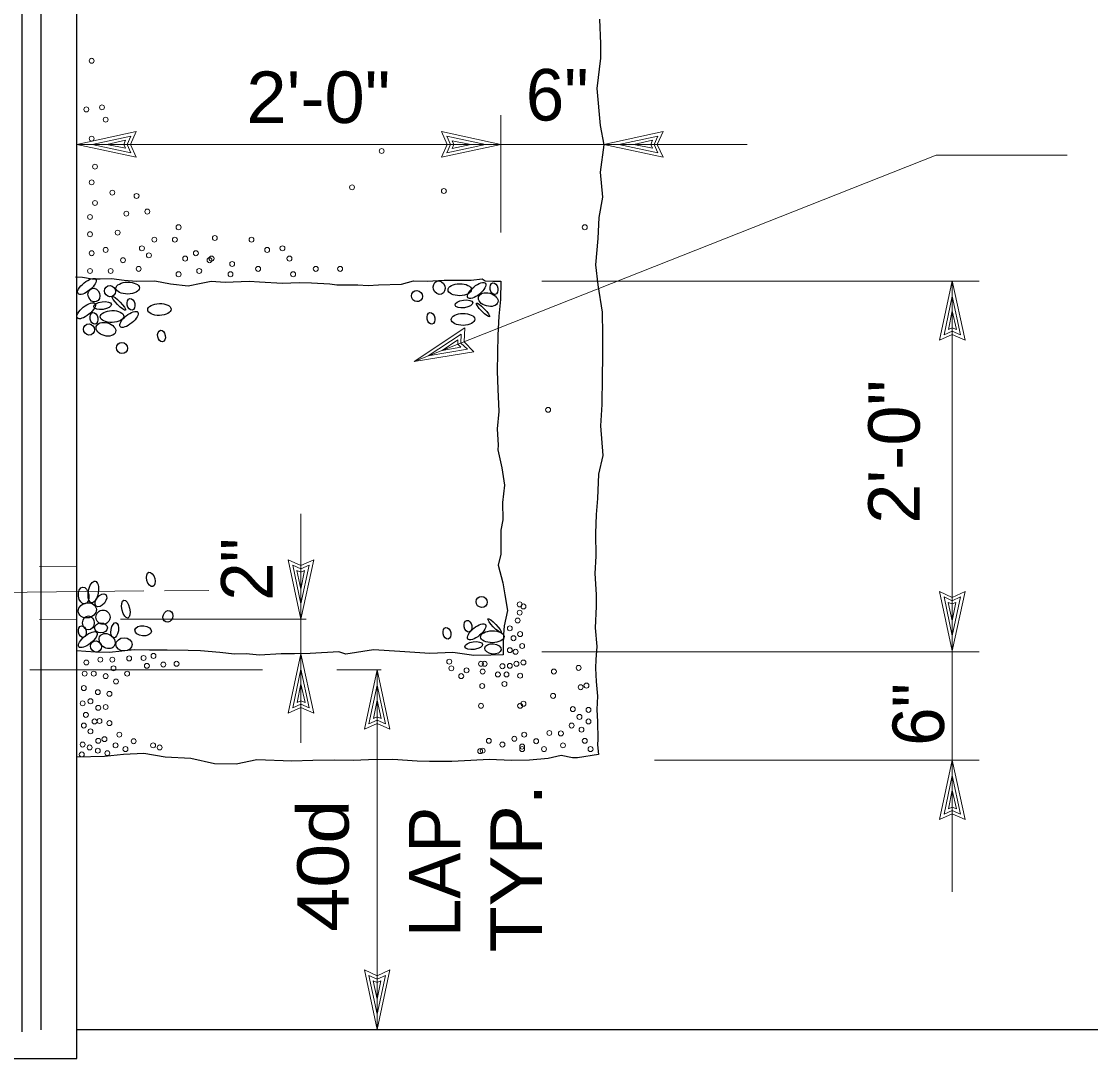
# Model space of a CAD drawing. Extents: x -28.1 to 13.9, y -16.1 to 13.9.
# Drawn here: x -6.926 to -4.33, y -10.785 to -8.269 of the extents above; entities that cross this region are included whole.
import ezdxf
from ezdxf.enums import TextEntityAlignment as Align

# ---------------------------------------------------------------- set-up
doc = ezdxf.new("R2010")
doc.units = 0
doc.header["$LTSCALE"] = 0.05
doc.linetypes.add('MEDIUM_DASHED', pattern=[4.5, 3, -1.5])
doc.layers.add('1', color=7, linetype='Continuous', lineweight=13)

msp = doc.modelspace()

# ---------------------------------------------------------------- linework, layer by layer
at = {"layer": '1', "lineweight": 25}
for p, q in [((-6.79104, -10.78531), (-6.79104, -2.71131)), ((-6.87804, -10.71531), (-6.87804, -2.77031)), ((-6.92404, -10.72031), (-6.92404, -6.69531)), ((-6.79004, -10.71431), (-2.77004, -10.71431)), ((-7.63204, -10.78531), (-6.79104, -10.78531))]:
    msp.add_line(p, q, dxfattribs=at)
at = {"layer": '1'}
for p, q in [((-5.76204, -8.78131), (-5.76204, -8.49631)), ((-6.79104, -8.56731), (-6.64704, -8.53631)), ((-5.76204, -8.56731), (-5.90604, -8.53631)), ((-5.51204, -8.56731), (-5.36804, -8.53631)), ((-6.75404, -8.56731), (-6.66004, -8.54731)), ((-6.71804, -8.56731), (-6.67304, -8.55731)), ((-6.67304, -8.55731), (-6.67704, -8.56731)), ((-6.66004, -8.54731), (-6.66904, -8.56731)), ((-5.79904, -8.56731), (-5.89304, -8.54731)), ((-5.88404, -8.56731), (-5.89304, -8.54731)), ((-5.83504, -8.56731), (-5.88004, -8.55831)), ((-5.87604, -8.56731), (-5.88004, -8.55831)), ((-5.47504, -8.56731), (-5.38104, -8.54731)), ((-5.43904, -8.56731), (-5.39404, -8.55731)), ((-5.39404, -8.55731), (-5.39804, -8.56731)), ((-5.38104, -8.54731), (-5.39004, -8.56731)), ((-6.79104, -8.56731), (-6.64704, -8.59831)), ((-6.75404, -8.56731), (-6.66004, -8.58731)), ((-6.71804, -8.56731), (-6.67304, -8.57631)), ((-6.67704, -8.56731), (-6.67304, -8.57631)), ((-6.66904, -8.56731), (-6.66004, -8.58731)), ((-5.76204, -8.56731), (-5.90604, -8.59831)), ((-5.79904, -8.56731), (-5.89304, -8.58731)), ((-5.89304, -8.58731), (-5.88404, -8.56731)), ((-5.83504, -8.56731), (-5.88004, -8.57731)), ((-5.88004, -8.57731), (-5.87604, -8.56731)), ((-5.51204, -8.56731), (-5.36804, -8.59831)), ((-5.47504, -8.56731), (-5.38104, -8.58731)), ((-5.43904, -8.56731), (-5.39404, -8.57631)), ((-5.39804, -8.56731), (-5.39404, -8.57631)), ((-5.39004, -8.56731), (-5.38104, -8.58731)), ((-4.70504, -8.59331), (-4.38704, -8.59331)), ((-5.66204, -8.89931), (-4.60104, -8.89931)), ((-4.66604, -8.89831), (-4.69704, -9.04231)), ((-4.66604, -8.89831), (-4.63504, -9.04231)), ((-4.66604, -8.93531), (-4.68604, -9.02931)), ((-4.66604, -8.93531), (-4.64604, -9.02931)), ((-4.66604, -8.97131), (-4.67504, -9.01631)), ((-4.66604, -8.97131), (-4.65604, -9.01631)), ((-5.93804, -9.08031), (-5.85804, -9.02731)), ((-5.85804, -9.02731), (-5.85904, -9.04931)), ((-4.66604, -9.02031), (-4.68604, -9.02931)), ((-4.66604, -9.01231), (-4.67504, -9.01631)), ((-4.65604, -9.01631), (-4.66604, -9.01231)), ((-4.64604, -9.02931), (-4.66604, -9.02031)), ((-5.90404, -9.06731), (-5.86604, -9.04131)), ((-5.86604, -9.04131), (-5.86604, -9.05231)), ((-5.86604, -9.05231), (-5.85904, -9.05931)), ((-5.85904, -9.04931), (-5.84304, -9.06431)), ((-5.97204, -9.09431), (-5.82704, -9.07031)), ((-5.93804, -9.08031), (-5.84304, -9.06431)), ((-5.90404, -9.06731), (-5.85904, -9.05931)), ((-6.24704, -9.71931), (-6.27804, -9.57531)), ((-6.24704, -9.71931), (-6.21604, -9.57531)), ((-6.24704, -9.68231), (-6.26704, -9.58831)), ((-6.26704, -9.58831), (-6.24704, -9.59731)), ((-6.24704, -9.64631), (-6.25704, -9.60131)), ((-6.25704, -9.60131), (-6.24704, -9.60531)), ((-6.24704, -9.68231), (-6.22704, -9.58831)), ((-6.24704, -9.59731), (-6.22704, -9.58831)), ((-6.24704, -9.64631), (-6.23804, -9.60131)), ((-6.24704, -9.60531), (-6.23804, -9.60131)), ((-7.10304, -9.65531), (-6.62804, -9.65031)), ((-6.57804, -9.65031), (-6.47104, -9.64931)), ((-4.66604, -9.79631), (-4.69704, -9.65231)), ((-4.66604, -9.79631), (-4.63504, -9.65231)), ((-4.66604, -9.75931), (-4.68604, -9.66531)), ((-4.68604, -9.66531), (-4.66604, -9.67431)), ((-4.66604, -9.72331), (-4.67604, -9.67831)), ((-4.67604, -9.67831), (-4.66604, -9.68231)), ((-4.66604, -9.75931), (-4.64604, -9.66531)), ((-4.66604, -9.67431), (-4.64604, -9.66531)), ((-4.66604, -9.72331), (-4.65704, -9.67831)), ((-4.66604, -9.68231), (-4.65704, -9.67831)), ((-6.68504, -9.71931), (-6.23404, -9.71931)), ((-6.24704, -9.80331), (-6.27804, -9.94731)), ((-6.24704, -9.80331), (-6.21604, -9.94731)), ((-5.66204, -9.79831), (-4.60104, -9.79831)), ((-6.90504, -9.84231), (-6.34004, -9.84231)), ((-6.24704, -9.84031), (-6.26704, -9.93431)), ((-6.24704, -9.84031), (-6.22704, -9.93431)), ((-6.16004, -9.84231), (-6.05204, -9.84231)), ((-6.06204, -9.84231), (-6.09304, -9.98631)), ((-6.06204, -10.71431), (-6.06204, -9.84231)), ((-6.06204, -9.84231), (-6.03104, -9.98631)), ((-6.24704, -9.87631), (-6.25604, -9.92131)), ((-6.24704, -9.87631), (-6.23704, -9.92131)), ((-6.06204, -9.87931), (-6.08204, -9.97331)), ((-6.06204, -9.87931), (-6.04204, -9.97331)), ((-6.24704, -9.92531), (-6.26704, -9.93431)), ((-6.24704, -9.91731), (-6.25604, -9.92131)), ((-6.23704, -9.92131), (-6.24704, -9.91731)), ((-6.22704, -9.93431), (-6.24704, -9.92531)), ((-6.06204, -9.91531), (-6.07104, -9.96031)), ((-6.06204, -9.91531), (-6.05204, -9.96031)), ((-6.06204, -9.96431), (-6.08204, -9.97331)), ((-6.06204, -9.95631), (-6.07104, -9.96031)), ((-6.05204, -9.96031), (-6.06204, -9.95631)), ((-6.04204, -9.97331), (-6.06204, -9.96431)), ((-5.38904, -10.06131), (-4.60104, -10.06131)), ((-4.66604, -10.06131), (-4.69704, -10.20531)), ((-4.66604, -10.06131), (-4.63504, -10.20531)), ((-4.66604, -10.09831), (-4.68604, -10.19231)), ((-4.66604, -10.09831), (-4.64604, -10.19231)), ((-4.66604, -10.13431), (-4.67504, -10.17931)), ((-4.66604, -10.13431), (-4.65604, -10.17931)), ((-4.66604, -10.18331), (-4.68604, -10.19231)), ((-4.66604, -10.17531), (-4.67504, -10.17931)), ((-4.65604, -10.17931), (-4.66604, -10.17531)), ((-4.64604, -10.19231), (-4.66604, -10.18331)), ((-6.06204, -10.71431), (-6.09304, -10.57031)), ((-6.06204, -10.67731), (-6.08204, -10.58331)), ((-6.08204, -10.58331), (-6.06204, -10.59231)), ((-6.06204, -10.71431), (-6.03104, -10.57031)), ((-6.06204, -10.67731), (-6.04204, -10.58331)), ((-6.06204, -10.59231), (-6.04204, -10.58331)), ((-6.06204, -10.64131), (-6.07204, -10.59631)), ((-6.07204, -10.59631), (-6.06204, -10.60031)), ((-6.06204, -10.64131), (-6.05304, -10.59631)), ((-6.06204, -10.60031), (-6.05304, -10.59631))]:
    msp.add_line(p, q, dxfattribs=at)
at = {"layer": '1', "linetype": 'MEDIUM_DASHED'}
for p, q in [((-7.63204, -9.59831), (-6.79104, -9.59031)), ((-7.63204, -9.72731), (-6.79104, -9.71931))]:
    msp.add_line(p, q, dxfattribs=at)
at = {"layer": '1', "lineweight": 25}
for points in [[(-5.52204, -8.26331), (-5.52004, -8.32331), (-5.52004, -8.35831), (-5.52904, -8.43131), (-5.52104, -8.52131), (-5.51204, -8.56831), (-5.52104, -8.63431), (-5.51504, -8.69531), (-5.52404, -8.74431), (-5.52604, -8.79531), (-5.53204, -8.85931), (-5.52604, -8.90831), (-5.51604, -8.97431), (-5.51504, -9.02931), (-5.51504, -9.08131), (-5.51604, -9.13231), (-5.51704, -9.19831), (-5.52004, -9.25031), (-5.51404, -9.32231), (-5.52504, -9.36731), (-5.52704, -9.42631), (-5.53004, -9.46531), (-5.53204, -9.51131), (-5.53104, -9.56631), (-5.53404, -9.60831), (-5.53004, -9.65931), (-5.53004, -9.68831), (-5.53304, -9.74031), (-5.52904, -9.78531), (-5.53104, -9.81731), (-5.53204, -9.83831), (-5.53004, -9.87031), (-5.52704, -9.90631), (-5.52904, -9.93831), (-5.52704, -9.96831), (-5.52604, -10.01031), (-5.52704, -10.02431), (-5.52504, -10.04731), (-5.57604, -10.05531), (-5.58804, -10.05531), (-5.61504, -10.05031), (-5.64704, -10.05731), (-5.69204, -10.06131), (-5.73604, -10.06231), (-5.79004, -10.05931), (-5.83504, -10.06231), (-5.88104, -10.06431), (-5.93504, -10.06431), (-5.96504, -10.06331), (-6.02404, -10.05931), (-6.08304, -10.06031), (-6.12004, -10.06231), (-6.16604, -10.06131), (-6.21804, -10.06231), (-6.26904, -10.06331), (-6.35404, -10.06031), (-6.40404, -10.07131), (-6.45704, -10.07031)], [(-6.79404, -8.88831), (-6.77704, -8.88931), (-6.75404, -8.89331), (-6.73404, -8.89331), (-6.70704, -8.89231), (-6.67604, -8.89631), (-6.64604, -8.89931), (-6.60204, -8.89831), (-6.56404, -8.90531), (-6.52104, -8.91031), (-6.48904, -8.90431), (-6.46504, -8.89931), (-6.43104, -8.90131), (-6.37304, -8.89931), (-6.34804, -8.90031), (-6.29204, -8.90431), (-6.25104, -8.90231), (-6.22104, -8.90331), (-6.17704, -8.90531), (-6.16004, -8.90831), (-6.10904, -8.90831), (-6.08404, -8.90931), (-6.05904, -8.90831), (-6.00304, -8.90631), (-5.97404, -8.89831), (-5.94104, -8.89931), (-5.89904, -8.89631), (-5.86504, -8.89631), (-5.83404, -8.89631), (-5.80704, -8.89331), (-5.80004, -8.89831), (-5.78104, -8.89931), (-5.76204, -8.89931), (-5.76304, -8.94331), (-5.76704, -8.98431), (-5.76904, -9.03031), (-5.77104, -9.11731), (-5.76904, -9.16131), (-5.76704, -9.21531), (-5.77104, -9.25731), (-5.76804, -9.29731), (-5.76904, -9.30831), (-5.75904, -9.35231), (-5.75304, -9.39431), (-5.75804, -9.43631), (-5.75704, -9.47831), (-5.76204, -9.50331), (-5.76204, -9.56131), (-5.76804, -9.58831), (-5.75704, -9.63131), (-5.75204, -9.66031), (-5.74604, -9.69831), (-5.75404, -9.73531), (-5.75504, -9.75631), (-5.75604, -9.78231), (-5.75604, -9.80531), (-5.78604, -9.80631), (-5.82704, -9.80731), (-5.87804, -9.80031), (-5.93404, -9.80231), (-6.00704, -9.79731), (-6.07104, -9.79331), (-6.13804, -9.80431), (-6.15504, -9.79831), (-6.22504, -9.80231), (-6.26304, -9.80331), (-6.29504, -9.80331), (-6.34804, -9.80631), (-6.38004, -9.80331), (-6.40804, -9.80431), (-6.44404, -9.80031), (-6.49104, -9.79631), (-6.52104, -9.79531), (-6.57204, -9.79431), (-6.61504, -9.79431), (-6.65204, -9.79331), (-6.71204, -9.80031), (-6.74604, -9.79931), (-6.76904, -9.79731), (-6.79104, -9.79631)], [(-6.45704, -10.07031), (-6.51404, -10.05731), (-6.57704, -10.05431), (-6.62804, -10.04531), (-6.67804, -10.04731), (-6.72404, -10.05231), (-6.79104, -10.05431)]]:
    msp.add_lwpolyline(points, dxfattribs=at)
at = {"layer": '1'}
for points in [[(-6.64704, -8.53631), (-6.66104, -8.56731), (-6.64704, -8.59831)], [(-5.90604, -8.59831), (-5.89204, -8.56731), (-5.90604, -8.53631)], [(-5.36804, -8.53631), (-5.38204, -8.56731), (-5.36804, -8.59831)], [(-6.79104, -8.56731), (-5.76204, -8.56731), (-5.51204, -8.56731), (-5.16404, -8.56731)], [(-4.70504, -8.59331), (-5.97204, -9.09431), (-5.84904, -9.01231)], [(-4.66604, -10.38031), (-4.66604, -10.06131), (-4.66604, -9.79631), (-4.66604, -8.89831)], [(-5.84904, -9.01231), (-5.85104, -9.04631), (-5.82704, -9.07031)], [(-4.63504, -9.04231), (-4.66604, -9.02831), (-4.69704, -9.04231)], [(-6.24704, -10.01931), (-6.24704, -9.80331), (-6.24704, -9.71931), (-6.24704, -9.46331)], [(-6.27804, -9.57531), (-6.24704, -9.58931), (-6.21604, -9.57531)], [(-4.69704, -9.65231), (-4.66604, -9.66631), (-4.63504, -9.65231)], [(-6.21604, -9.94731), (-6.24704, -9.93331), (-6.27804, -9.94731)], [(-6.03104, -9.98631), (-6.06204, -9.97231), (-6.09304, -9.98631)], [(-4.63504, -10.20531), (-4.66604, -10.19131), (-4.69704, -10.20531)], [(-6.09304, -10.57031), (-6.06204, -10.58431), (-6.03104, -10.57031)]]:
    msp.add_lwpolyline(points, dxfattribs=at)
for centre in [(-6.75504, -8.36431), (-6.76804, -8.48231), (-6.73004, -8.47731), (-6.72104, -8.50731), (-6.75504, -8.55331), (-6.05104, -8.58331), (-6.74704, -8.62131), (-6.75504, -8.65931), (-6.12304, -8.67131), (-6.70504, -8.68431), (-6.64604, -8.69231), (-5.90004, -8.68031), (-6.74704, -8.70931), (-6.75904, -8.74331), (-6.67104, -8.73531), (-6.62004, -8.73031), (-6.54404, -8.76831), (-5.55804, -8.76831), (-6.75904, -8.78531), (-6.69204, -8.78131), (-6.60304, -8.79831), (-6.55304, -8.79831), (-6.45604, -8.79431), (-6.36704, -8.79831), (-6.72104, -8.82331), (-6.63304, -8.81931), (-6.32904, -8.82331), (-6.29204, -8.81931), (-6.75504, -8.83131), (-6.67904, -8.84831), (-6.61604, -8.83631), (-6.52804, -8.84431), (-6.50204, -8.83131), (-6.46904, -8.84831), (-6.46404, -8.84431), (-6.27504, -8.84431), (-6.75904, -8.87431), (-6.70904, -8.87431), (-6.64104, -8.86931), (-6.54404, -8.88231), (-6.49404, -8.87431), (-6.41804, -8.88231), (-6.41404, -8.85731), (-6.35104, -8.86931), (-6.26604, -8.88231), (-6.21104, -8.86931), (-6.15204, -8.86931), (-5.64704, -9.21131), (-5.71604, -9.68331), (-5.71604, -9.70331), (-5.70704, -9.68831), (-5.72104, -9.72231), (-5.74004, -9.74131), (-5.71504, -9.75531), (-5.73104, -9.76531), (-5.71004, -9.78431), (-6.66404, -9.81431), (-6.62904, -9.81331), (-6.60504, -9.80831), (-5.74004, -9.79431), (-5.72604, -9.79831), (-6.76804, -9.82431), (-6.73404, -9.81731), (-6.70504, -9.81731), (-6.70204, -9.83831), (-6.62104, -9.83231), (-6.58104, -9.82931), (-6.54904, -9.82731), (-5.88704, -9.82231), (-5.88204, -9.83831), (-5.81004, -9.82731), (-5.80104, -9.82731), (-5.75804, -9.83331), (-5.74004, -9.83231), (-5.72404, -9.82731), (-5.70704, -9.82431), (-5.57304, -9.83731), (-6.77204, -9.85131), (-6.75004, -9.85131), (-6.72104, -9.85731), (-6.66904, -9.85131), (-5.85804, -9.85731), (-5.84504, -9.84331), (-5.80604, -9.84631), (-5.76904, -9.85331), (-5.74804, -9.85331), (-5.71504, -9.85631), (-5.63304, -9.84631), (-6.77404, -9.88631), (-6.69604, -9.87031), (-5.80704, -9.88131), (-5.75304, -9.87631), (-5.56804, -9.88431), (-5.55404, -9.88031), (-5.55404, -9.88031), (-6.75804, -9.91831), (-6.74004, -9.89631), (-6.71204, -9.90031), (-5.63504, -9.90531), (-6.77704, -9.92331), (-6.73904, -9.93431), (-6.72104, -9.93231), (-5.81004, -9.92931), (-5.71504, -9.92931), (-5.70704, -9.92431), (-5.58704, -9.93731), (-5.54904, -9.93931), (-6.76904, -9.95131), (-6.74804, -9.96731), (-6.73604, -9.96631), (-6.71204, -9.97131), (-5.57104, -9.95631), (-5.54904, -9.96731), (-6.77404, -9.97731), (-6.75804, -9.99131), (-5.64404, -9.99531), (-5.61604, -9.99631), (-5.59004, -9.97731), (-5.56604, -9.98731), (-6.77704, -10.02331), (-6.73904, -10.01431), (-6.72404, -10.01031), (-6.68804, -9.99931), (-6.65304, -10.01531), (-5.79104, -10.01431), (-5.75804, -10.02331), (-5.72904, -10.00931), (-5.70504, -9.99931), (-5.67604, -10.01531), (-5.55804, -10.01431), (-6.77904, -10.04731), (-6.76004, -10.03031), (-6.74004, -10.03831), (-6.71704, -10.04431), (-6.69704, -10.02531), (-6.67304, -10.03431), (-6.60604, -10.02531), (-6.59004, -10.03031), (-5.81204, -10.03931), (-5.80604, -10.03831), (-5.71004, -10.02831), (-5.71004, -10.03431), (-5.65704, -10.03431), (-5.61104, -10.02531), (-5.54404, -10.03431)]:
    msp.add_circle(centre, 0.006, dxfattribs=at)
at = {"layer": '1', "lineweight": 25}
for centre, major_axis, ratio in [((-6.76654, -8.91181), (0.0215, 0.0175), 0.397321), ((-6.66754, -8.91581), (0.0285, 0.0005), 0.506888), ((-5.91154, -8.91481), (-0.0053, 0.01589), 0.849837), ((-5.82054, -8.92181), (0.0215, 0.0175), 0.397321), ((-5.77854, -8.91731), (0.0025, -0.014), 0.662183), ((-6.74954, -8.93281), (-0.0053, 0.01589), 0.849837), ((-6.71054, -8.92331), (0.0095, -0.01), 0.956548), ((-5.96554, -8.93531), (0.0095, -0.01), 0.956548), ((-5.86154, -8.91981), (0.0285, 0.0005), 0.506888), ((-5.79254, -8.94381), (0.0235, -0.0065), 0.651283), ((-6.76854, -8.97081), (0.0215, 0.0175), 0.397321), ((-6.72854, -8.95831), (0.0215, 0.003), 0.431436), ((-6.68904, -8.95281), (0.016, -0.0165), 0.183852), ((-6.65954, -8.95531), (0.0025, -0.014), 0.662183), ((-6.59054, -8.96781), (0.0285, 0.0005), 0.506888), ((-5.85154, -8.95431), (0.0215, 0.003), 0.431436), ((-5.80504, -8.96881), (0.016, -0.0165), 0.183852), ((-6.74954, -8.98931), (0.0025, -0.014), 0.662183), ((-6.70554, -8.98481), (0.0285, 0.0005), 0.506888), ((-6.66454, -8.99181), (0.0215, 0.0175), 0.397321), ((-5.93154, -8.98931), (0.0025, -0.014), 0.662183), ((-5.85354, -8.99181), (0.0285, 0.0005), 0.506888), ((-6.76154, -9.01631), (0.0095, -0.01), 0.956548), ((-6.72054, -9.01581), (0.0235, -0.0065), 0.651283), ((-6.58554, -9.03231), (0.0025, -0.014), 0.662183), ((-6.68154, -9.06131), (0.0095, -0.01), 0.956548), ((-6.75104, -9.65331), (0.00436, 0.02616), 0.458731), ((-6.61154, -9.62281), (-0.00457, 0.01736), 0.547365), ((-6.77454, -9.66181), (-0.0025, 0.0205), 0.609614), ((-6.76554, -9.69781), (0.0215, 0.0055), 0.823552), ((-6.73254, -9.67331), (0.0115, 0.014), 0.602008), ((-6.67204, -9.69481), (-0.005, 0.0215), 0.422849), ((-5.80854, -9.67731), (0.0095, -0.01), 0.956548), ((-6.72754, -9.71431), (0.0065, -0.016), 0.982726), ((-6.57004, -9.71231), (0.00488, 0.01343), 0.819222), ((-6.76304, -9.72831), (0, 0.017), 0.829288), ((-6.73254, -9.74031), (-0.0155, 0), 0.781736), ((-6.69904, -9.74581), (-0.003, -0.0185), 0.48024), ((-5.84154, -9.73631), (0.0025, -0.014), 0.662183), ((-5.82054, -9.74981), (0.0215, 0.0175), 0.397321), ((-5.77704, -9.73481), (0.016, -0.0165), 0.183852), ((-6.76454, -9.76881), (0.0215, 0.0175), 0.397321), ((-6.77754, -9.74931), (0.0025, -0.014), 0.662183), ((-6.71754, -9.77231), (0.0165, -0.013), 0.788693), ((-6.63004, -9.74731), (-0.02, 0.002), 0.619845), ((-5.89254, -9.75331), (0.0025, -0.014), 0.662183), ((-5.78254, -9.76181), (0.0285, 0.0005), 0.506888), ((-6.74454, -9.78531), (0.0095, -0.01), 0.956548), ((-6.67654, -9.78031), (0.0195, 0), 0.820783), ((-5.82754, -9.78331), (0.0215, 0.003), 0.431436), ((-5.78104, -9.79131), (-0.02, 0.002), 0.619845)]:
    msp.add_ellipse(centre, major_axis=major_axis, ratio=ratio, dxfattribs=at)

# ---------------------------------------------------------------- texts
at = {"layer": '1'}
msp.add_text('6"', height=0.125, dxfattribs=at).set_placement((-5.70104, -8.50931))
at = {"layer": '1', "width": 1.05}
msp.add_text('2\'-0"', height=0.125, dxfattribs=at).set_placement((-6.20469, -8.51531), align=Align.CENTER)
at = {"layer": '1'}
for s, width, p in [('2\'-0"', 1.05, (-4.74504, -9.31296)), ('TYP.', 1.1, (-5.66204, -10.32354)), ('40d', 1.15, (-6.13104, -10.31744))]:
    msp.add_text(s, height=0.125, rotation=90, dxfattribs=dict(at, width=width)).set_placement(p, align=Align.CENTER)
for s, p in [('2"', (-6.31604, -9.67431)), ('6"', (-4.68604, -10.02631))]:
    msp.add_text(s, height=0.125, rotation=90, dxfattribs=at).set_placement(p)
msp.add_text('LAP', height=0.125, rotation=90, dxfattribs=at).set_placement((-5.86004, -10.33236), align=Align.CENTER)

doc.saveas('drawing.dxf')
